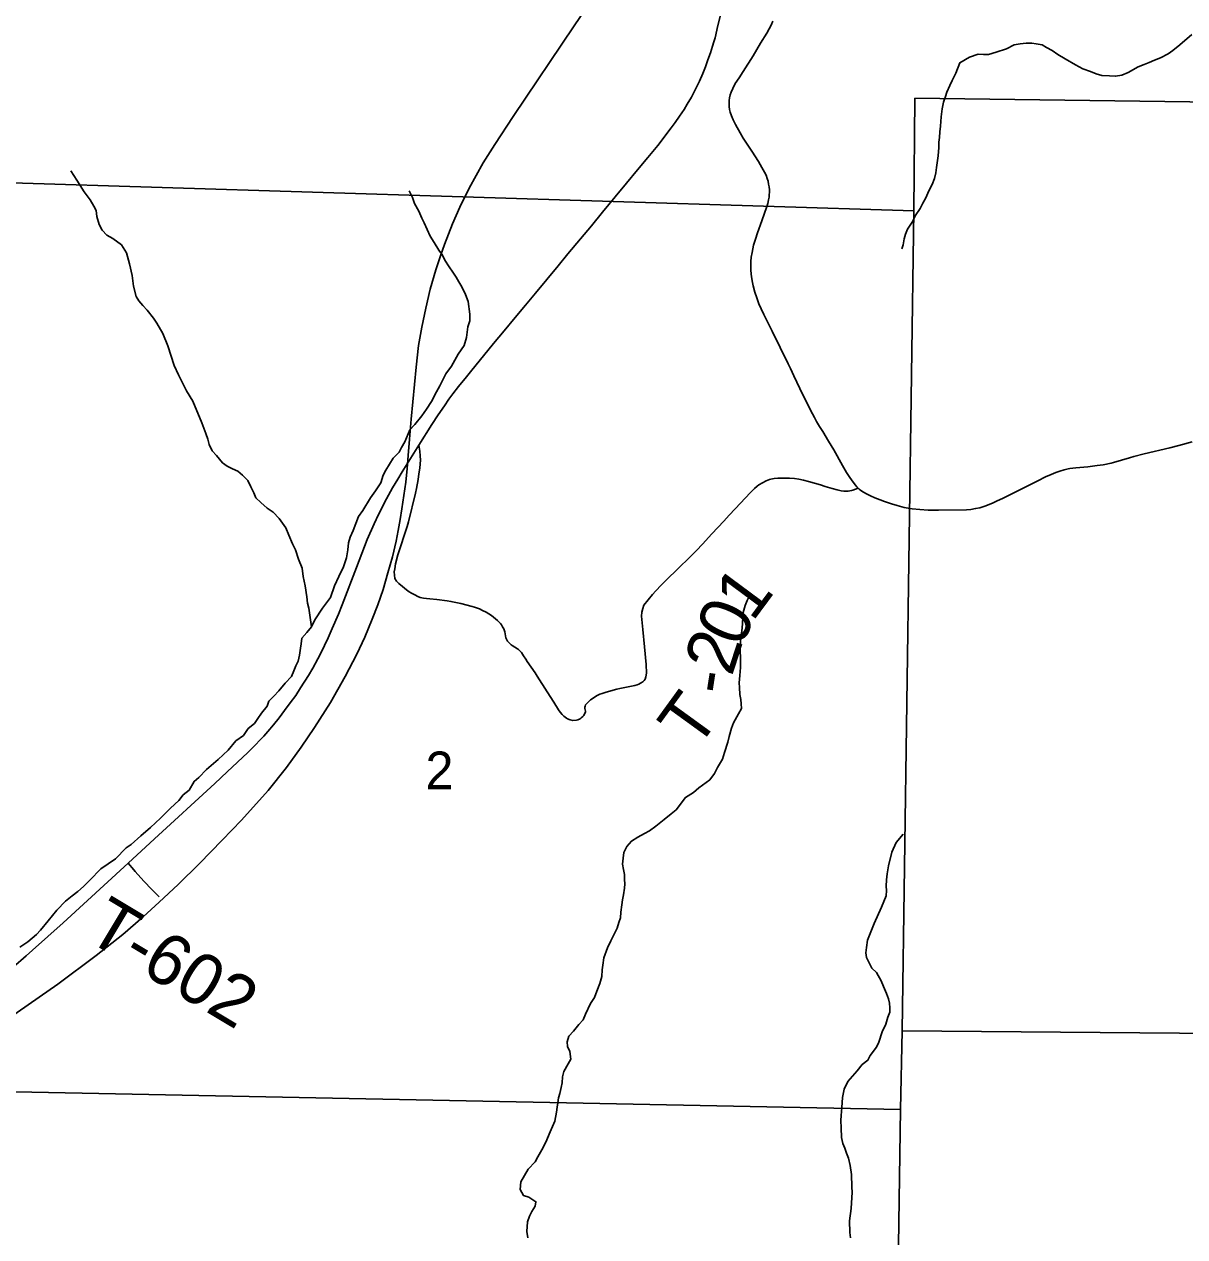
# Model space of a CAD drawing. Extents: x -7.1 to 34, y 0 to 22.
# Drawn here: x 2.831 to 4.122, y 15.53 to 16.88 of the extents above; entities that cross this region are included whole.
import ezdxf

# ---------------------------------------------------------------- set-up
doc = ezdxf.new("R2010")
doc.units = 0
for name, color, linetype in [('GM_X_County_Road', 7, 'Continuous'), ('GM_X_Minor_River', 7, 'Continuous'), ('GM_X_Rail_Line', 7, 'Continuous'), ('GM_X_Section', 7, 'Continuous'), ('GM_X_Section_Text', 7, 'Continuous'), ('GM_X_State_Route', 7, 'Continuous'), ('GM_X_Township_Road', 7, 'Continuous'), ('GM_X_Township_Road_Text', 7, 'Continuous')]:
    doc.layers.add(name, color=color, linetype=linetype)

msp = doc.modelspace()

# ---------------------------------------------------------------- linework, layer by layer
at = {"layer": 'GM_X_County_Road'}
for points in [[(3.6636, 16.8833), (3.6617, 16.8792), (3.6595, 16.875), (3.6567, 16.8701), (3.65, 16.8588), (3.6415, 16.8449), (3.6305, 16.8276), (3.6259, 16.8205), (3.6218, 16.8142), (3.6189, 16.8086), (3.617, 16.8045), (3.616, 16.8013), (3.6152, 16.7982), (3.6149, 16.795), (3.615, 16.7884), (3.6155, 16.7851), (3.6161, 16.7822), (3.6174, 16.7782), (3.6194, 16.7736), (3.622, 16.7685), (3.6271, 16.7591), (3.6307, 16.7532), (3.6403, 16.7386), (3.6476, 16.7272), (3.6514, 16.7207), (3.6542, 16.7155), (3.656, 16.7119), (3.6573, 16.7085), (3.6582, 16.7052), (3.6589, 16.7022), (3.6594, 16.699), (3.6597, 16.6956), (3.6593, 16.6875), (3.6588, 16.6846), (3.6578, 16.6804), (3.6568, 16.6771), (3.6512, 16.6611), (3.6463, 16.6477), (3.6441, 16.6409), (3.6422, 16.6341), (3.6404, 16.6261), (3.6396, 16.6207), (3.6391, 16.6161), (3.6389, 16.6113), (3.639, 16.6066), (3.6394, 16.6019), (3.64, 16.5967), (3.6409, 16.5924), (3.6417, 16.5888), (3.6436, 16.5817), (3.6456, 16.5754), (3.6481, 16.5688), (3.6504, 16.5633), (3.6535, 16.5571), (3.6627, 16.5383), (3.6805, 16.5022)], [(3.6805, 16.5022), (3.6832, 16.4968), (3.6869, 16.4888), (3.6936, 16.4744), (3.7017, 16.458), (3.7077, 16.4464), (3.7098, 16.4423), (3.7122, 16.4377), (3.7154, 16.4324), (3.719, 16.4266), (3.7254, 16.416), (3.7315, 16.4062), (3.7412, 16.389), (3.7455, 16.3812), (3.7492, 16.3753), (3.7509, 16.3727), (3.755, 16.3673), (3.7571, 16.365), (3.7586, 16.3635), (3.7597, 16.3625), (3.7616, 16.3609), (3.7645, 16.359), (3.7677, 16.3572), (3.7721, 16.3551), (3.7769, 16.3529), (3.7828, 16.3506), (3.7879, 16.3488), (3.7957, 16.3462), (3.802, 16.3443), (3.8096, 16.3422), (3.8185, 16.3407), (3.8272, 16.3397), (3.8364, 16.3393), (3.8478, 16.3391), (3.8791, 16.3395), (3.8839, 16.3399), (3.8891, 16.3408), (3.8939, 16.3419), (3.8993, 16.3434), (3.9024, 16.3445), (3.9087, 16.3471), (3.9126, 16.349), (3.9197, 16.3524), (3.9583, 16.3719), (3.967, 16.3762), (3.9732, 16.379), (3.9783, 16.381), (3.9828, 16.3827), (3.9876, 16.3841), (3.9922, 16.3852), (3.9941, 16.3855), (4.0006, 16.3862), (4.014, 16.3875), (4.0246, 16.3887), (4.031, 16.3897), (4.0399, 16.3913), (4.0425, 16.392), (4.0604, 16.3975), (4.0653, 16.3989), (4.0767, 16.4018), (4.1054, 16.4086), (4.1152, 16.411), (4.1302, 16.4151)]]:
    msp.add_lwpolyline(points, dxfattribs=at)
at = {"layer": 'GM_X_Minor_River'}
for points in [[(4.1299, 16.8685), (4.1165, 16.8572), (4.1086, 16.851), (4.1033, 16.8471), (4.0951, 16.8428), (4.0883, 16.84), (4.0823, 16.8373), (4.0766, 16.8353), (4.0702, 16.8325), (4.059, 16.8263), (4.0518, 16.8235), (4.045, 16.8222), (4.0382, 16.8225), (4.0295, 16.8231), (4.0234, 16.825), (4.0169, 16.8275), (4.0085, 16.8304), (4.0005, 16.8349), (3.9887, 16.8416), (3.9807, 16.8464), (3.9742, 16.8509), (3.9681, 16.8542), (3.9631, 16.8572), (3.9567, 16.8582), (3.9517, 16.8589), (3.9453, 16.8588), (3.9389, 16.8583), (3.9321, 16.8571), (3.9234, 16.8527), (3.9121, 16.8488), (3.9034, 16.8464), (3.8978, 16.8463), (3.8921, 16.8466), (3.8823, 16.8434), (3.8718, 16.8371), (3.867, 16.8256), (3.863, 16.8176), (3.8604, 16.8118), (3.8571, 16.8045), (3.8556, 16.7996), (3.8535, 16.7934), (3.8521, 16.7858), (3.851, 16.777), (3.8501, 16.7667), (3.8494, 16.7602), (3.8491, 16.7541), (3.8484, 16.7488), (3.8481, 16.7427), (3.8475, 16.7336), (3.8465, 16.7259), (3.8458, 16.7206), (3.8451, 16.7145), (3.8433, 16.7084), (3.8408, 16.7015)], [(3.15, 16.2093), (3.1471, 16.2302), (3.1459, 16.2355), (3.1451, 16.2428), (3.143, 16.2549), (3.141, 16.2652), (3.1397, 16.2747), (3.1358, 16.2845), (3.1322, 16.2951), (3.1291, 16.3015), (3.1251, 16.3114), (3.1216, 16.3193), (3.1143, 16.3298), (3.1074, 16.337), (3.1008, 16.3414), (3.0939, 16.3478), (3.0882, 16.353), (3.0862, 16.3583), (3.0827, 16.3651), (3.0792, 16.3723), (3.0734, 16.3779), (3.0681, 16.3824), (3.0624, 16.385), (3.0563, 16.388), (3.0513, 16.3917), (3.0443, 16.4), (3.0397, 16.4052), (3.0362, 16.4124), (3.035, 16.4181), (3.0326, 16.4245), (3.0283, 16.4362), (3.0181, 16.4605), (3.0111, 16.4721), (3.006, 16.4823), (3.0021, 16.4899), (2.9974, 16.5001), (2.9903, 16.5221), (2.9848, 16.5357), (2.9782, 16.5474), (2.9743, 16.553), (2.9674, 16.5617), (2.9624, 16.5669), (2.9582, 16.5722), (2.9551, 16.5771), (2.9522, 16.5885), (2.9506, 16.6003), (2.9477, 16.6132), (2.9445, 16.6257), (2.9387, 16.6343), (2.9291, 16.6414), (2.9226, 16.6451), (2.9173, 16.6508), (2.9138, 16.6572), (2.9114, 16.6659), (2.9105, 16.6727), (2.9078, 16.6776), (2.9039, 16.6844), (2.8973, 16.6935), (2.8892, 16.7063), (2.8822, 16.7168)], [(3.8408, 16.7015), (3.8371, 16.6946), (3.8338, 16.6869), (3.8305, 16.6808), (3.8275, 16.675), (3.822, 16.6669), (3.8194, 16.6608), (3.8135, 16.652), (3.8113, 16.6462), (3.8098, 16.6412), (3.8084, 16.6344), (3.807, 16.6299)], [(3.0574, 16.072), (3.066, 16.0824), (3.0746, 16.0883), (3.0798, 16.096), (3.0869, 16.1018), (3.0906, 16.1072), (3.0947, 16.113), (3.1007, 16.121), (3.1028, 16.1264), (3.1081, 16.1322), (3.114, 16.138), (3.1207, 16.1465), (3.1278, 16.1538), (3.1307, 16.1603), (3.1326, 16.1657), (3.1355, 16.1711), (3.1369, 16.1776), (3.138, 16.1856), (3.1386, 16.1905), (3.1393, 16.1966), (3.1449, 16.2028), (3.1501, 16.2093), (3.1538, 16.217), (3.1623, 16.2301), (3.1712, 16.242), (3.1756, 16.255), (3.1807, 16.2654), (3.1859, 16.2761), (3.1891, 16.2861), (3.1905, 16.2949), (3.1915, 16.3029), (3.1933, 16.309), (3.1966, 16.3163), (3.2025, 16.332), (3.2073, 16.3389), (3.2158, 16.3527), (3.2214, 16.3608), (3.2273, 16.3696), (3.2298, 16.3781), (3.2328, 16.3838), (3.2409, 16.3969), (3.2476, 16.4038), (3.2502, 16.4088), (3.2539, 16.4153), (3.2597, 16.4284), (3.2653, 16.4346), (3.2728, 16.4442), (3.278, 16.4515), (3.2839, 16.46), (3.2894, 16.4707), (3.2931, 16.4776), (3.2997, 16.4907), (3.306, 16.4995), (3.3134, 16.5126), (3.3201, 16.5226), (3.3226, 16.5314), (3.3243, 16.5432), (3.3265, 16.5497), (3.3264, 16.5573), (3.3247, 16.5714), (3.3215, 16.5793), (3.3173, 16.5876), (3.3142, 16.5933), (3.311, 16.5986), (3.3076, 16.6042), (3.3033, 16.6099), (3.2987, 16.6174), (3.2959, 16.6231), (3.2917, 16.6287), (3.2866, 16.637), (3.2824, 16.6442), (3.2789, 16.6514), (3.2757, 16.6589), (3.273, 16.6642), (3.2695, 16.6718), (3.2648, 16.6805), (3.2624, 16.6873), (3.2589, 16.6945)], [(3.6274, 16.1938), (3.6288, 16.2022), (3.6295, 16.2079), (3.6298, 16.2133), (3.6301, 16.2198), (3.6307, 16.2251), (3.6329, 16.2331), (3.6351, 16.2385), (3.6363, 16.2417)], [(3.391, 15.5291), (3.3897, 15.5363), (3.3907, 15.5469), (3.3929, 15.5531), (3.3955, 15.5584), (3.3992, 15.5642), (3.3999, 15.5692), (3.3922, 15.5744), (3.3861, 15.5762), (3.3822, 15.583), (3.3833, 15.5914), (3.3873, 15.5983), (3.3914, 15.6056), (3.3992, 15.6137), (3.4022, 15.6194), (3.4066, 15.6271), (3.411, 15.6356), (3.4158, 15.647), (3.4209, 15.6589), (3.423, 15.6689), (3.4237, 15.6746), (3.4244, 15.6795), (3.4251, 15.6849), (3.4265, 15.6898), (3.4279, 15.6963), (3.429, 15.7017), (3.4296, 15.7082), (3.4311, 15.7143), (3.4359, 15.7227), (3.4388, 15.7281), (3.4376, 15.7364), (3.4352, 15.7421), (3.4348, 15.7471), (3.4366, 15.7536), (3.4418, 15.7593), (3.4477, 15.7667), (3.4526, 15.7717), (3.4551, 15.7782), (3.4606, 15.7901), (3.4651, 15.7966), (3.4676, 15.8035), (3.4709, 15.8123), (3.4731, 15.82), (3.4737, 15.8276), (3.4744, 15.8325), (3.4754, 15.8409), (3.4794, 15.852), (3.4831, 15.8597), (3.4871, 15.867), (3.4905, 15.8739), (3.4923, 15.88), (3.4941, 15.8854), (3.4944, 15.8915), (3.4954, 15.8999), (3.4964, 15.9052), (3.4975, 15.9109), (3.4985, 15.9182), (3.4988, 15.9231), (3.4984, 15.9281), (3.4983, 15.9334), (3.4975, 15.9391), (3.4962, 15.9452), (3.4969, 15.9516), (3.4979, 15.9581), (3.5012, 15.9647), (3.5061, 15.9708), (3.5132, 15.9751), (3.5207, 15.979), (3.5264, 15.9822), (3.5335, 15.9872), (3.5428, 15.9946), (3.5503, 16.0012), (3.5559, 16.0055), (3.5663, 16.0193), (3.5753, 16.0248), (3.5813, 16.0302), (3.5933, 16.0391), (3.5985, 16.0461), (3.6018, 16.0526), (3.6074, 16.0618), (3.6099, 16.0695), (3.6135, 16.0809), (3.6149, 16.0871), (3.6175, 16.0966), (3.6196, 16.1024), (3.6252, 16.1123), (3.6285, 16.1185), (3.6284, 16.1234), (3.628, 16.1284), (3.6268, 16.1341), (3.6263, 16.1417), (3.6262, 16.147), (3.6268, 16.155), (3.6275, 16.1641), (3.6277, 16.1702), (3.6277, 16.1756), (3.6272, 16.1816), (3.6274, 16.1938)], [(2.8255, 15.8527), (2.8345, 15.8585), (2.8442, 15.8666), (2.8487, 15.8717), (2.8573, 15.8821), (2.8669, 15.894), (2.8763, 15.9037), (2.8837, 15.9099), (2.8901, 15.9145), (2.8965, 15.92), (2.9036, 15.9273), (2.9159, 15.9397), (2.932, 15.951), (2.9439, 15.9633), (2.9496, 15.9668), (2.9604, 15.9765), (2.9712, 15.9858), (2.9821, 15.9963), (2.9933, 16.0075), (3.0026, 16.016), (3.0074, 16.0222), (3.0142, 16.0276), (3.0197, 16.0372), (3.0249, 16.0415), (3.0335, 16.0503), (3.0462, 16.0616), (3.0574, 16.072)], [(3.7901, 15.9158), (3.7896, 15.9207), (3.7899, 15.9276), (3.7906, 15.9341), (3.7924, 15.9432), (3.7959, 15.9585), (3.8007, 15.9692), (3.8085, 15.9785)], [(3.7499, 15.5292), (3.7491, 15.5349), (3.7489, 15.5479), (3.7506, 15.5616), (3.7512, 15.5681), (3.7518, 15.5795), (3.7514, 15.586), (3.7512, 15.5997), (3.7495, 15.6095), (3.7479, 15.6179), (3.7455, 15.6232), (3.7435, 15.6289), (3.7416, 15.6342), (3.74, 15.6406), (3.7394, 15.6516), (3.7393, 15.6596), (3.7396, 15.6653), (3.7402, 15.6741), (3.7412, 15.6852), (3.743, 15.6947), (3.747, 15.7031), (3.7574, 15.7151), (3.763, 15.722), (3.7694, 15.7267), (3.772, 15.7321), (3.779, 15.7413), (3.7816, 15.747), (3.7852, 15.7585), (3.7892, 15.767), (3.7914, 15.7746), (3.7936, 15.7803), (3.7939, 15.7853), (3.7934, 15.7902), (3.7922, 15.7952), (3.7899, 15.8012), (3.7867, 15.8088), (3.784, 15.8152), (3.7789, 15.8243), (3.7736, 15.8291), (3.7677, 15.8412), (3.7669, 15.8462), (3.7679, 15.8523), (3.7689, 15.8603), (3.7762, 15.879), (3.7843, 15.8971), (3.7898, 15.9097), (3.7901, 15.9158)]]:
    msp.add_lwpolyline(points, dxfattribs=at)
at = {"layer": 'GM_X_Rail_Line'}
msp.add_lwpolyline([(2.8142, 15.7738), (2.868, 15.8115), (2.9107, 15.8432), (2.9402, 15.8667), (2.963, 15.8863), (2.9808, 15.9026), (3.0019, 15.9224), (3.0256, 15.9459), (3.0508, 15.9717), (3.0724, 15.994), (3.1021, 16.0269), (3.1223, 16.0528), (3.1387, 16.0753), (3.1537, 16.0972), (3.1713, 16.1249), (3.1876, 16.1539), (3.2007, 16.179), (3.2096, 16.1979), (3.2177, 16.2176), (3.2239, 16.2338), (3.23, 16.2508), (3.2352, 16.2692), (3.2402, 16.2873), (3.2444, 16.3047), (3.2468, 16.3164), (3.249, 16.3288), (3.2508, 16.3405), (3.255, 16.3704), (3.2565, 16.3854), (3.2577, 16.4001), (3.2594, 16.4182), (3.2611, 16.4403), (3.2665, 16.4982), (3.2693, 16.5225), (3.2729, 16.543), (3.2773, 16.564), (3.2822, 16.5853), (3.2885, 16.6066), (3.2942, 16.6233), (3.2981, 16.635), (3.3071, 16.6578), (3.3154, 16.6766), (3.3255, 16.6974), (3.3413, 16.7257), (3.3542, 16.7462), (3.3747, 16.7775), (3.4423, 16.8782), (3.5421, 17.0257)], dxfattribs=at)
at = {"layer": 'GM_X_Section'}
for points in [[(3.8217, 16.7978), (4.6565, 16.7868), (4.645, 15.7523), (3.8073, 15.7595), (3.8205, 16.6723)], [(3.8205, 16.6723), (3.8073, 15.7595), (3.8055, 15.6719), (2.8016, 15.6921), (2.8168, 16.7036)], [(4.645, 15.7523), (4.6234, 14.7351), (3.7918, 14.7389), (3.8055, 15.6719), (3.8073, 15.7595)], [(2.8016, 15.6921), (3.8055, 15.6719), (3.7918, 14.7389), (3.7909, 14.6711), (2.7883, 14.6781)]]:
    msp.add_lwpolyline(points, close=True, dxfattribs=at)
at = {"layer": 'GM_X_State_Route'}
msp.add_lwpolyline([(2.8183, 15.8304), (2.8328, 15.8431), (2.8399, 15.8493), (2.8738, 15.8799), (2.9462, 15.946), (2.9756, 15.9734), (3.0425, 16.0349), (3.0565, 16.048), (3.0793, 16.0693), (3.0835, 16.0734), (3.0972, 16.0877), (3.1016, 16.0926), (3.108, 16.1002), (3.1141, 16.1081), (3.1202, 16.1161), (3.1265, 16.1245), (3.1326, 16.1329), (3.1381, 16.1413), (3.1467, 16.1551), (3.1515, 16.1633), (3.1574, 16.1738), (3.1609, 16.1805), (3.1647, 16.1884), (3.1686, 16.1969), (3.1733, 16.2075), (3.1801, 16.2234), (3.1842, 16.2339), (3.2001, 16.2752), (3.2123, 16.3066), (3.2199, 16.324), (3.2246, 16.3344), (3.2336, 16.3519), (3.2403, 16.3639), (3.2462, 16.3738), (3.2512, 16.3818), (3.2698, 16.4115), (3.284, 16.4344), (3.2912, 16.4451), (3.298, 16.4554), (3.303, 16.4626), (3.3074, 16.4686), (3.3138, 16.4769), (3.3226, 16.4875), (3.3287, 16.495), (3.3414, 16.5108), (3.3526, 16.5246), (3.3647, 16.5388), (3.3769, 16.5537), (3.3884, 16.5674), (3.3995, 16.5808), (3.4121, 16.5958), (3.4246, 16.6111), (3.4355, 16.6243), (3.4495, 16.6413), (3.4616, 16.6556), (3.474, 16.6709), (3.4881, 16.688), (3.5006, 16.703), (3.513, 16.718), (3.5244, 16.7316), (3.5355, 16.7452), (3.5503, 16.7646), (3.5549, 16.7706), (3.5598, 16.7778), (3.5647, 16.7851), (3.5682, 16.7909), (3.573, 16.799), (3.578, 16.8086), (3.5818, 16.8167), (3.5856, 16.8252), (3.5886, 16.8328), (3.5913, 16.8406), (3.594, 16.8484), (3.5964, 16.8555), (3.5979, 16.8603), (3.5992, 16.8651), (3.6025, 16.8785), (3.6053, 16.8902)], dxfattribs=at)
at = {"layer": 'GM_X_Township_Road'}
for points in [[(3.2698, 16.4115), (3.2707, 16.4049), (3.2712, 16.3997), (3.2714, 16.3949), (3.2712, 16.3908), (3.2707, 16.386), (3.2698, 16.3795), (3.2689, 16.3734), (3.267, 16.3633), (3.2659, 16.3581), (3.258, 16.3262), (3.2566, 16.3209), (3.2464, 16.2894), (3.2437, 16.2792), (3.2428, 16.2737), (3.2423, 16.2705), (3.243, 16.2632), (3.2448, 16.2601), (3.2472, 16.2576)], [(3.2472, 16.2576), (3.2516, 16.254), (3.256, 16.2505), (3.259, 16.2482), (3.2615, 16.2467), (3.265, 16.2447), (3.2684, 16.243), (3.2712, 16.242), (3.2748, 16.2412), (3.278, 16.2407), (3.282, 16.2404), (3.2897, 16.2396), (3.3011, 16.2382), (3.3053, 16.2375), (3.3164, 16.2353), (3.3291, 16.2319), (3.3316, 16.2312), (3.3371, 16.2292), (3.3406, 16.2276), (3.3446, 16.2257), (3.3477, 16.2238), (3.3504, 16.2219), (3.3551, 16.2182), (3.3573, 16.2162), (3.3606, 16.2128), (3.3615, 16.2116), (3.3629, 16.2092), (3.3642, 16.2069), (3.3649, 16.2047), (3.3653, 16.2036), (3.3666, 16.197), (3.3671, 16.1956), (3.3683, 16.1933), (3.3689, 16.1925), (3.3725, 16.1891), (3.3733, 16.1884), (3.3795, 16.1847), (3.3806, 16.184), (3.3829, 16.1819), (3.3838, 16.1808), (3.3862, 16.1771), (3.3887, 16.1731), (3.3901, 16.1707), (3.3989, 16.1582), (3.4014, 16.1545), (3.4124, 16.1369), (3.4197, 16.1254), (3.425, 16.117), (3.4269, 16.1144), (3.4293, 16.1115), (3.4311, 16.1098), (3.4338, 16.1076), (3.4352, 16.1068), (3.438, 16.1056), (3.4396, 16.1052), (3.4409, 16.1049), (3.445, 16.1052), (3.4464, 16.1057), (3.4491, 16.107), (3.4503, 16.1078), (3.4523, 16.1095), (3.4532, 16.1106), (3.4545, 16.1131), (3.4549, 16.1142), (3.455, 16.1152), (3.4545, 16.1185), (3.4544, 16.1198), (3.4546, 16.1209), (3.4552, 16.1223), (3.4559, 16.1233), (3.4592, 16.1266), (3.4608, 16.1278), (3.466, 16.1315), (3.4674, 16.1323), (3.4712, 16.1342), (3.4737, 16.1352), (3.4781, 16.1366), (3.4899, 16.1397), (3.4933, 16.1405), (3.5099, 16.1439), (3.5125, 16.1447), (3.5144, 16.1455), (3.5164, 16.1466), (3.5188, 16.148), (3.5203, 16.1495), (3.5213, 16.1509), (3.5222, 16.1537), (3.5231, 16.1578), (3.5226, 16.1673), (3.5206, 16.1871), (3.5188, 16.2062), (3.5174, 16.2212), (3.5176, 16.2257), (3.5188, 16.2296), (3.5201, 16.2332), (3.5298, 16.2451), (3.5334, 16.2493), (3.5393, 16.2555), (3.545, 16.2613), (3.5582, 16.274), (3.5711, 16.2867), (3.5787, 16.2944), (3.5851, 16.3011), (3.5958, 16.3127), (3.6089, 16.3269), (3.6151, 16.3335), (3.6216, 16.3405), (3.6388, 16.3588), (3.643, 16.3631), (3.646, 16.3658), (3.648, 16.3673), (3.652, 16.3696), (3.6562, 16.3717), (3.6597, 16.3731), (3.6613, 16.3736), (3.6652, 16.3742), (3.6691, 16.3746), (3.677, 16.3749), (3.6822, 16.3746), (3.6877, 16.3742), (3.6925, 16.3736), (3.6976, 16.3725), (3.7033, 16.371), (3.7165, 16.3673), (3.7219, 16.3656), (3.7295, 16.3632), (3.7352, 16.3616), (3.7396, 16.3606), (3.7424, 16.3602), (3.7474, 16.3603), (3.7512, 16.3609), (3.7525, 16.3613), (3.7586, 16.3635)], [(2.9805, 15.9085), (2.9725, 15.9169), (2.9636, 15.9262), (2.954, 15.9367), (2.9523, 15.9387), (2.9462, 15.946)]]:
    msp.add_lwpolyline(points, dxfattribs=at)

# ---------------------------------------------------------------- texts
at = {"layer": 'GM_X_Section_Text'}
msp.add_text('2', height=0.0419, rotation=0, dxfattribs=at).set_placement((3.277, 16.0285))
at = {"layer": 'GM_X_Township_Road_Text'}
for s, height, rotation, p in [('1', 0.0568, 53.4351, (3.6408, 16.2139)), ('0', 0.0568, 65.6069, (3.6279, 16.1848)), ('2', 0.0568, 72.067, (3.6178, 16.1531)), ('-', 0.0568, 81.1849, (3.6147, 16.1324)), ('T', 0.0568, 54.0533, (3.5787, 16.0711)), ('T-602', 0.05682, 329.0364, (2.8969, 15.8623))]:
    msp.add_text(s, height=height, rotation=rotation, dxfattribs=at).set_placement(p)

doc.saveas('drawing.dxf')
